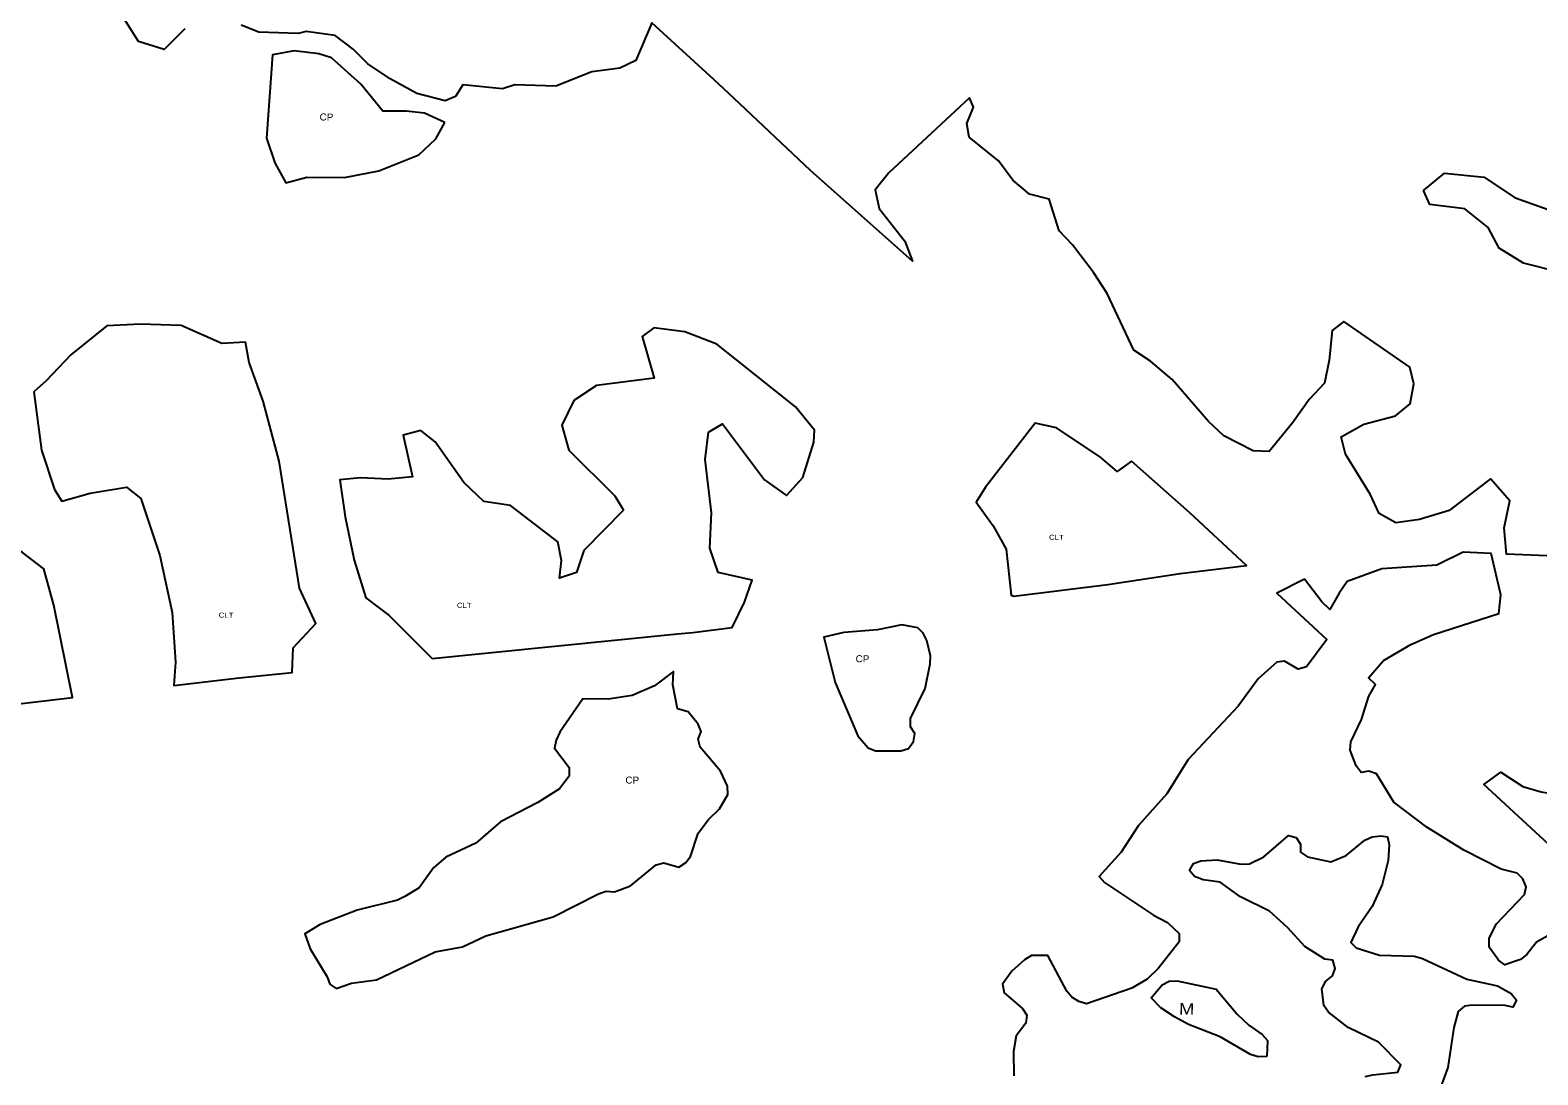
# Model space of a CAD drawing. Extents: x 713589 to 726391, y 7177764 to 7191819.
# Drawn here: x 715078 to 716445, y 7181525 to 7182472 of the extents above; entities that cross this region are included whole.
import ezdxf
from ezdxf.enums import TextEntityAlignment as Align

# ---------------------------------------------------------------- set-up
doc = ezdxf.new("R2010")
doc.units = 0
doc.header["$LTSCALE"] = 2.6
doc.layers.add('63', color=7, linetype='Continuous', lineweight=25)

msp = doc.modelspace()

# ---------------------------------------------------------------- linework, layer by layer
at = {"layer": '63'}
for points in [[(715218.27, 7182473.44), (715199.35, 7182454.58), (715176.33, 7182461.68), (715143.77, 7182513.34)], [(716146, 7182117.24), (716113.23, 7182155.26), (716093.42, 7182172.05), (716078.39, 7182181.99), (716054.38, 7182233.38), (716041.98, 7182252.37), (716022.86, 7182277.37), (716010.92, 7182290.04), (716001.66, 7182318.93), (715983.88, 7182323.41), (715968.85, 7182336.09), (715955.88, 7182353.55), (715929.24, 7182375.14), (715927.21, 7182387.46), (715933.05, 7182402.16), (715929.64, 7182410.71), (715856.34, 7182342.77), (715844, 7182327.4), (715847.73, 7182310.29), (715870.94, 7182280.84), (715877.88, 7182262.64), (715785.27, 7182344.81), (715716.03, 7182410.2), (715697.84, 7182427.38), (715641.56, 7182478.67), (715627.12, 7182444.46), (715612.53, 7182437.53), (715587.01, 7182434.26), (715554.51, 7182421.38), (715517.39, 7182422.44), (715506.11, 7182418.81), (715470.33, 7182422.52), (715463.68, 7182411.92), (715454.07, 7182407.96), (715428.56, 7182414.63), (715404.39, 7182427.93), (715384.19, 7182441.55), (715370.96, 7182454.83), (715354.41, 7182467.12), (715328.29, 7182470.94), (715321, 7182468.97), (715303.13, 7182469.66), (715285.21, 7182470.35), (715269.32, 7182476.67)], [(716467.72, 7181994.81), (716416.39, 7181997.1), (716414.06, 7182020.89), (716419.3, 7182045.25), (716401.75, 7182065.17), (716364.42, 7182036.5), (716337.39, 7182028.34), (716315.84, 7182025.29), (716300.8, 7182033.87), (716292.62, 7182051.33), (716270.45, 7182087.62), (716266.37, 7182103.36), (716286.91, 7182114.95), (716315.66, 7182122.43), (716329.01, 7182133.35), (716332.12, 7182151.47), (716328.73, 7182166.53), (716268.94, 7182208.01), (716258.32, 7182199.82), (716255.54, 7182172.81), (716251.4, 7182151.95), (716237.36, 7182137.27), (716222.61, 7182116.43), (716201.02, 7182090.13), (716186.66, 7182090.83), (716160, 7182104.22), (716146, 7182117.24)], [(715018.75, 7181855.45), (715116.49, 7181867.04), (715099.62, 7181950.87), (715090.4, 7181983.7), (715071.2, 7181998.64), (715031.47, 7182019.92), (715006.64, 7182035.54), (714990.41, 7182042.85), (714973.81, 7182036.47), (714971.51, 7182035.59), (714944.63, 7182014.76), (714911.12, 7181994.6), (714882.59, 7181974.76), (714876.91, 7181948.59), (714884.78, 7181898.2), (714897.28, 7181844.51), (714953.97, 7181849.54)], [(716456.47, 7181652.6), (716443.54, 7181645.33), (716434.57, 7181634.08), (716428.93, 7181629.44), (716414.67, 7181624.5), (716409.04, 7181628.82), (716400.44, 7181640.76), (716400.46, 7181648.71), (716407.11, 7181661.96), (716432.67, 7181688.43), (716434.01, 7181695.39), (716431.04, 7181702.68), (716426.07, 7181707.66), (716411.5, 7181711.33), (716377.72, 7181728.62), (716343.95, 7181749.56), (716314.16, 7181772.14), (716298.3, 7181797.69), (716291.34, 7181800.35), (716284.38, 7181799.04), (716280.08, 7181805.01), (716274.47, 7181819.27), (716275.15, 7181826.89), (716284.79, 7181847.09), (716291.46, 7181868.29), (716297.57, 7181878.82), (716291.16, 7181884.74), (716304.62, 7181900.68), (716329.61, 7181915), (716350.14, 7181924.2), (716409.35, 7181943.26), (716411.08, 7181960.02), (716402.42, 7181997.72), (716376.9, 7181998.86), (716352.99, 7181987.13), (716303.39, 7181983.79), (716271.9, 7181972.22), (716264.7, 7181961.63), (716256.12, 7181946.93), (716248.95, 7181953.79), (716233.18, 7181974.29), (716208, 7181961.55), (716253.32, 7181919.69), (716234.83, 7181894.9), (716227.53, 7181892.59), (716214.95, 7181899.9), (716207.99, 7181898.92), (716191.06, 7181884.03), (716173.13, 7181859.21), (716127.64, 7181810.9), (716108.37, 7181779.77), (716082.8, 7181750.98), (716066.86, 7181726.82), (716046.93, 7181704.65), (716051.9, 7181699.34), (716096.26, 7181669.77), (716108.84, 7181663.12), (716119.43, 7181653.16), (716119.41, 7181645.53), (716100.82, 7181621.7), (716090.53, 7181611.78), (716076.59, 7181603.52), (716035.47, 7181589.33), (716028.52, 7181591.33), (716022.23, 7181595.32), (716017.6, 7181600.63), (716000.42, 7181633.14), (715985.84, 7181633.16), (715979.2, 7181629.2), (715967.92, 7181618.94), (715959.28, 7181607.02), (715960.92, 7181599.4), (715977.47, 7181585.12), (715981.44, 7181579.15), (715980.43, 7181571.86), (715971.8, 7181560.27)], [(716288.23, 7181523.29), (716295.19, 7181524.94), (716317.73, 7181527.22), (716320.4, 7181533.85), (716300.21, 7181554.43), (716272.73, 7181567.73), (716254.86, 7181581.68), (716250.56, 7181587.65), (716248.93, 7181602.9), (716252.58, 7181609.85), (716258.56, 7181614.81), (716260.89, 7181621.44), (716258.91, 7181628.73), (716251.62, 7181629.74), (716233.41, 7181641.37), (716218.2, 7181658.3), (716201.32, 7181673.24), (716175.16, 7181686.21), (716156.62, 7181699.49), (716141.38, 7181701.84), (716133.43, 7181704.83), (716128.8, 7181710.14), (716132.46, 7181716.44), (716139.09, 7181719.08), (716154, 7181719.71), (716175.54, 7181716.03), (716183.16, 7181716.35), (716196.43, 7181722.63), (716218.67, 7181741.81), (716225.62, 7181740.14), (716229.59, 7181734.17), (716229.58, 7181726.88), (716235.87, 7181722.56), (716257.07, 7181717.89), (716271, 7181723.83), (716287.93, 7181737.72), (716294.56, 7181740.69), (716302.51, 7181741.67), (716308.37, 7181740.64), (716309.79, 7181733.37), (716309.1, 7181719.12), (716303.43, 7181697.59), (716294.45, 7181677.39), (716281.83, 7181659.18), (716275.18, 7181644.94), (716280.14, 7181639.97), (716301.01, 7181633.3), (716332.82, 7181632.59), (716340.11, 7181630.25), (716380.18, 7181611.63), (716408.01, 7181605.62), (716420.59, 7181598.64), (716425.22, 7181592.66), (716421.9, 7181586.37), (716414.94, 7181587.71), (716385.11, 7181588.09), (716378.15, 7181587.11), (716372.51, 7181582.48), (716368.51, 7181567.9), (716363.15, 7181531.46), (716349.83, 7181495.35)], [(715971.8, 7181560.27), (715969.45, 7181546.03), (715969.75, 7181524.15)]]:
    msp.add_lwpolyline(points, dxfattribs=at)
for points in [[(715454.03, 7182388.41), (715435.49, 7182396.73), (715418.92, 7182398.74), (715397.71, 7182398.78), (715377.87, 7182423), (715351.06, 7182446.91), (715339.8, 7182450.57), (715317.27, 7182453.26), (715297.84, 7182449.64), (715292.28, 7182374.1), (715299.87, 7182351.88), (715309.78, 7182333.63), (715328.68, 7182338.91), (715362.81, 7182338.52), (715393.97, 7182344.43), (715430.45, 7182358.95), (715445.72, 7182373.51)], [(716340.89, 7182326.79), (716360.07, 7182342.49), (716395.98, 7182338.67), (716423.65, 7182320.49), (716458.18, 7182308.12), (716496.44, 7182282.41), (716515.58, 7182273.48), (716515.16, 7182271.49), (716491.96, 7182258.13), (716465.27, 7182252.36), (716431.76, 7182260.97), (716409.55, 7182274.34), (716399.67, 7182293.17), (716378.49, 7182309.96), (716346.69, 7182314.12)], [(715081.39, 7182144.11), (715088.26, 7182091.41), (715100.13, 7182055.6), (715106.74, 7182044.98), (715132.27, 7182052.23), (715165.42, 7182057.81), (715178.33, 7182047.51), (715195.48, 7181995.78), (715206.66, 7181944.07), (715209.9, 7181898.99), (715208.27, 7181877.92), (715267.37, 7181884.93), (715315.5, 7181889.75), (715316.3, 7181912.07), (715336.89, 7181934.24), (715322.03, 7181966.08), (715303.66, 7182081.44), (715289.17, 7182135.82), (715276.63, 7182170.64), (715273.35, 7182189.2), (715251.8, 7182187.91), (715215.04, 7182204.21), (715177.93, 7182205.6), (715147.44, 7182203.99), (715114.91, 7182177.86), (715092.67, 7182154.04)], [(715615.84, 7182036.84), (715579.99, 7182000.45), (715573.33, 7181980.24), (715557.97, 7181975.34), (715559.66, 7181991.25), (715556.47, 7182008.11), (715513.44, 7182040.99), (715489.26, 7182044.68), (715471.06, 7182061.94), (715445.27, 7182098.77), (715432.03, 7182109.07), (715416.11, 7182104.78), (715424.67, 7182066.99), (715402.46, 7182065.04), (715377.61, 7182066.07), (715358.71, 7182064.45), (715363.63, 7182030.97), (715371.85, 7181991.51), (715382.4, 7181957.36), (715403.58, 7181941.42), (715442.4, 7181902.45), (715664.77, 7181924.71), (715678.73, 7181926.11), (715714.27, 7181930.63), (715725.4, 7181953.48), (715732.39, 7181973.35), (715701.58, 7181980.36), (715694, 7182002.58), (715695.71, 7182034.39), (715689.82, 7182082.79), (715692.85, 7182107.64), (715705.45, 7182115.24), (715743.81, 7182064.47), (715763.67, 7182050.19), (715778.28, 7182066.4), (715788.28, 7182098.53), (715788.96, 7182109.47), (715771.76, 7182130.71), (715700.6, 7182187.5), (715671.46, 7182198.48), (715643.29, 7182202.17), (715632.67, 7182194.24), (715643.55, 7182156.44), (715591.5, 7182149.9), (715570.93, 7182136.34), (715559.96, 7182113.83), (715566.22, 7182091.28), (715607.91, 7182049.78)], [(715962.77, 7182001.47), (715967.34, 7181959.71), (715969.57, 7181958.94), (716054.87, 7181969.34), (716120.33, 7181979.53), (716180.66, 7181986.8), (716129.17, 7182034.36), (716076.48, 7182081.18), (716063.31, 7182071.9), (716048.41, 7182084.51), (716008.36, 7182111.42), (715989.14, 7182115.77), (715943.97, 7182057.84), (715935.67, 7182044.27), (715950.88, 7182022.7)], [(715875.89, 7181848.1), (715889.19, 7181875.25), (715893.87, 7181897.45), (715894.21, 7181904.74), (715890.92, 7181918.67), (715887.62, 7181925.3), (715882.66, 7181930.28), (715868.08, 7181932.95), (715846.2, 7181928.35), (715815.7, 7181926.08), (715797.38, 7181921.82), (715807.67, 7181880.69), (715828.14, 7181832.27), (715837.73, 7181821.32), (715844.36, 7181818.66), (715867.23, 7181818.62), (715874.19, 7181820.93), (715878.84, 7181827.22), (715879.85, 7181834.51), (715875.88, 7181840.48)], [(715445.04, 7181636.38), (715469.9, 7181640.98), (715491.13, 7181650.89), (715552.13, 7181668.02), (715593.26, 7181689.16), (715600.23, 7181691.47), (715607.85, 7181690.79), (715622.11, 7181696.4), (715645.34, 7181715.26), (715652.3, 7181717.23), (715665.88, 7181713.23), (715672.19, 7181717.2), (715676.5, 7181722.83), (715683.5, 7181744.02), (715692.8, 7181756.27), (715702.76, 7181766.2), (715710.4, 7181779.11), (715710.08, 7181786.73), (715703.81, 7181800.33), (715685.29, 7181821.9), (715683.64, 7181829.2), (715686.3, 7181836.15), (715683.66, 7181842.79), (715674.4, 7181854.07), (715664.85, 7181856.63), (715660.71, 7181878.63), (715661.32, 7181890.55), (715643.95, 7181877.65), (715623.72, 7181868.73), (715601.84, 7181865.46), (715578.98, 7181865.83), (715558.05, 7181835.7), (715554.72, 7181828.42), (715553.38, 7181821.13), (715566.61, 7181803.54), (715566.6, 7181795.59), (715557.96, 7181784.33), (715538.06, 7181771.77), (715504.22, 7181754.26), (715481.99, 7181735.08), (715454.79, 7181722.2), (715443.51, 7181712.61), (715430.55, 7181694.4), (715417.61, 7181686.47), (715410.98, 7181683.17), (715374.51, 7181674.28), (715341.01, 7181661.08), (715327.08, 7181652.81), (715331.7, 7181639.22), (715347.23, 7181613.67), (715349.54, 7181607.04), (715355.5, 7181603.06), (715369.43, 7181608), (715391.97, 7181610.95)], [(716490.44, 7181754.33), (716480.83, 7181736.56), (716489.78, 7181701.29), (716395.73, 7181788.16), (716411.11, 7181799.34), (716430.98, 7181786.23), (716447.73, 7181781.42), (716468.24, 7181778.3), (716492.17, 7181771.08)], [(716199.11, 7181541.67), (716191.16, 7181541.35), (716184.2, 7181543.35), (716156.72, 7181559.31), (716127.91, 7181570.62), (716115.33, 7181577.6), (716103.08, 7181585.58), (716094.02, 7181594.66), (716104.11, 7181606.45), (716110.41, 7181609.76), (716117.7, 7181610.08), (716153.15, 7181602.73), (716172, 7181579.83), (716182.59, 7181569.87), (716194.84, 7181561.56), (716199.47, 7181555.92)]]:
    msp.add_lwpolyline(points, close=True, dxfattribs=at)

# ---------------------------------------------------------------- texts
for s, height, width, p in [('CP', 6.4, 1.05, (715346.57, 7182390.15)), ('CLT', 4.64, 1.15, (716008.28, 7182009.91)), ('CLT', 4.64, 1.15, (715255.61, 7181939.32)), ('CLT', 4.64, 1.15, (715471.52, 7181948.29)), ('CP', 6.4, 1.05, (715832.44, 7181898.93)), ('CP', 6.4, 1.05, (715623.75, 7181788.92)), ('M', 10.4, 1.2, (716126.28, 7181579.46))]:
    msp.add_text(s, height=height, rotation=359.062, dxfattribs=dict(at, width=width)).set_placement(p, align=Align.CENTER)

doc.saveas('drawing.dxf')
